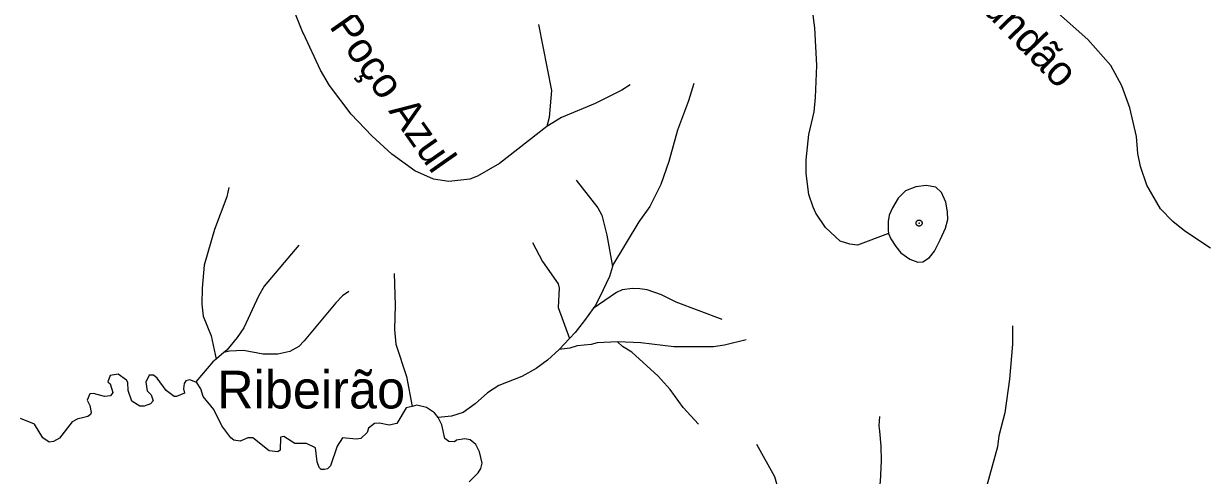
# Model space of a CAD drawing. Extents: x 393 to 446.6, y 8175.5 to 8231.
# Drawn here: x 405.92 to 412.17, y 8208.07 to 8210.46 of the extents above; entities that cross this region are included whole.
import ezdxf
from ezdxf.enums import TextEntityAlignment as Align

# ---------------------------------------------------------------- set-up
doc = ezdxf.new("R2010")
doc.units = 0
doc.header["$LTSCALE"] = 0.064
doc.header["$PDMODE"] = 32
doc.header["$PDSIZE"] = 0.032
doc.linetypes.add('LONG_DASHED', pattern=[7.5, 6, -1.5])
for name, color, linetype, lineweight in [('3', 7, 'LONG_DASHED', 25), ('7', 7, 'Continuous', 25), ('9', 7, 'LONG_DASHED', 25)]:
    doc.layers.add(name, color=color, linetype=linetype, lineweight=lineweight)
doc.layers.add('61', color=7, linetype='Continuous')

msp = doc.modelspace()

# ---------------------------------------------------------------- linework, layer by layer
at = {"layer": '3'}
msp.add_lwpolyline([(410.5024, 8209.3478), (410.514, 8209.3198), (410.5416, 8209.2799), (410.5672, 8209.2461), (410.6153, 8209.2124), (410.6582, 8209.196), (410.6848, 8209.198), (410.7186, 8209.2216), (410.7462, 8209.2543), (410.7759, 8209.3147), (410.8045, 8209.3771), (410.8168, 8209.4221), (410.8148, 8209.463), (410.8055, 8209.5142), (410.783, 8209.5653), (410.7534, 8209.594), (410.7012, 8209.6032), (410.647, 8209.596), (410.5928, 8209.5735), (410.5539, 8209.5356), (410.5232, 8209.4845), (410.5058, 8209.4446), (410.5007, 8209.4119), (410.5007, 8209.3668)], close=True, dxfattribs=at)
msp.add_point((410.664, 8209.4036), dxfattribs=at)
at = {"layer": '7'}
for p, q in [((408.8118, 8208.7912), (408.7567, 8208.734)), ((406.9814, 8208.7171), (406.9403, 8208.6832))]:
    msp.add_line(p, q, dxfattribs=at)
for points in [[(409.4706, 8210.1427), (409.443, 8210.0503), (409.3849, 8209.8952), (409.338, 8209.7289), (409.296, 8209.6078), (409.2379, 8209.4915), (409.1798, 8209.4108), (409.0408, 8209.1786), (409.0393, 8209.1736)], [(408.8478, 8209.6304), (408.9618, 8209.4851), (408.9828, 8209.4463), (409.0102, 8209.3397), (409.0393, 8209.1736)], [(407.0083, 8209.5914), (406.9966, 8209.5432), (406.932, 8209.3688), (406.8771, 8209.1799), (406.8658, 8209.0588), (406.8642, 8208.9748), (406.8722, 8208.9102), (406.9142, 8208.8069), (406.9403, 8208.6832)], [(408.6156, 8209.3002), (408.6695, 8209.1992), (408.7519, 8209.0814), (408.7583, 8209.0588), (408.7519, 8208.9554), (408.8114, 8208.7922), (408.8118, 8208.7912)], [(407.3787, 8209.2865), (407.1952, 8209.0685), (407.1645, 8209.0168), (407.087, 8208.8488), (407.0515, 8208.7972), (406.9965, 8208.7296), (406.9814, 8208.7171)], [(407.8828, 8209.1361), (407.888, 8208.9683), (407.8847, 8208.8392), (407.8928, 8208.7616), (407.9493, 8208.5905), (407.9787, 8208.4323)], [(409.0393, 8209.1736), (409.0234, 8209.1205), (408.9733, 8209.0122), (408.9488, 8208.9657), (408.9381, 8208.951)], [(409.6206, 8208.893), (409.3768, 8208.985), (409.2993, 8209.0232), (409.2234, 8209.0506), (409.1847, 8209.0555), (409.1459, 8209.0571), (409.091, 8209.049), (409.0619, 8209.0361), (408.9382, 8208.951), (408.9381, 8208.951)], [(407.6435, 8209.0412), (407.6097, 8209.018), (407.5747, 8208.9812), (407.4068, 8208.7794), (407.3777, 8208.7503), (407.3309, 8208.7229), (407.2663, 8208.7083), (407.1888, 8208.7099), (407.0854, 8208.7293), (407.0111, 8208.7245), (406.9814, 8208.7171)], [(408.9381, 8208.951), (408.8923, 8208.8876), (408.8423, 8208.823), (408.8118, 8208.7912)], [(409.0673, 8208.7738), (408.9586, 8208.7697), (408.9263, 8208.76), (408.852, 8208.7535), (408.8133, 8208.7406), (408.7567, 8208.734)], [(409.7485, 8208.7858), (409.6336, 8208.7568), (409.5754, 8208.7487), (409.3655, 8208.7487), (409.1895, 8208.7697), (409.0673, 8208.7738)], [(409.4964, 8208.3379), (409.4139, 8208.4258), (409.3461, 8208.5227), (409.2815, 8208.5921), (409.1427, 8208.7196), (409.0926, 8208.7503), (409.0673, 8208.7738)], [(406.9403, 8208.6832), (406.922, 8208.668), (406.8328, 8208.5617), (406.8324, 8208.5613)], [(408.7567, 8208.734), (408.6954, 8208.6776), (408.6356, 8208.6324), (408.5597, 8208.5904), (408.4386, 8208.5436), (408.3773, 8208.5048), (408.3127, 8208.4451), (408.2497, 8208.3999), (408.1867, 8208.3805), (408.1158, 8208.3731)], [(406.8324, 8208.5613), (406.8005, 8208.573), (406.7802, 8208.5679), (406.7705, 8208.5533), (406.7673, 8208.5259), (406.7721, 8208.5033), (406.7302, 8208.4855), (406.7173, 8208.4855), (406.6752, 8208.5162), (406.6284, 8208.5824), (406.609, 8208.5969), (406.5848, 8208.5985), (406.5671, 8208.5614), (406.5751, 8208.5146), (406.5961, 8208.4935), (406.6058, 8208.4613), (406.5929, 8208.4451), (406.559, 8208.4338), (406.5364, 8208.4338), (406.4944, 8208.4596), (406.4734, 8208.5162), (406.4718, 8208.5581), (406.4653, 8208.5711), (406.4217, 8208.6034), (406.3781, 8208.5953), (406.3668, 8208.563), (406.3781, 8208.5517), (406.3927, 8208.5065), (406.3814, 8208.4887), (406.3491, 8208.4839), (406.2909, 8208.5), (406.2715, 8208.4984), (406.257, 8208.4645), (406.2715, 8208.437), (406.278, 8208.3999), (406.2748, 8208.3886), (406.2602, 8208.3789), (406.2259, 8208.3706), (406.207, 8208.366), (406.1779, 8208.3499), (406.1101, 8208.2643), (406.0778, 8208.2465), (406.0552, 8208.2433), (406.0213, 8208.2659), (405.9777, 8208.3386), (405.9034, 8208.3676)], [(407.9787, 8208.4323), (407.9477, 8208.4241), (407.8977, 8208.3418), (407.8573, 8208.3321), (407.8056, 8208.3434), (407.7798, 8208.3418), (407.7477, 8208.3166), (407.7395, 8208.2933), (407.7071, 8208.2627), (407.6829, 8208.2594), (407.6102, 8208.2659), (407.5811, 8208.2223), (407.5456, 8208.1173), (407.5295, 8208.1012), (407.515, 8208.0979), (407.4972, 8208.0979), (407.4859, 8208.1093), (407.4746, 8208.1383), (407.4665, 8208.2126), (407.4181, 8208.2352), (407.3567, 8208.2352), (407.2986, 8208.2723), (407.2808, 8208.2691), (407.2792, 8208.2013), (407.2679, 8208.1916), (407.221, 8208.1964), (407.1339, 8208.2659), (407.108, 8208.2659), (407.0676, 8208.2481), (407.0337, 8208.253), (407.0176, 8208.2659), (406.9708, 8208.3289), (406.9272, 8208.4161), (406.8723, 8208.4839), (406.8593, 8208.5259), (406.8354, 8208.5602), (406.8324, 8208.5613)], [(408.1158, 8208.3731), (408.0962, 8208.3983), (408.0543, 8208.4258), (408.0026, 8208.4386), (407.9787, 8208.4323)], [(408.2803, 8208.0333), (408.3288, 8208.0802), (408.3417, 8208.1028), (408.3498, 8208.1319), (408.3353, 8208.1916), (408.3159, 8208.2303), (408.2868, 8208.2546), (408.2578, 8208.261), (408.2141, 8208.253), (408.2028, 8208.2449), (408.1722, 8208.2465), (408.1512, 8208.2626), (408.135, 8208.3353), (408.1158, 8208.3731)]]:
    msp.add_lwpolyline(points, dxfattribs=at)
at = {"layer": '9'}
for points in [[(408.6926, 8209.915), (408.4419, 8209.7192), (408.3256, 8209.6514), (408.2836, 8209.6368), (408.1738, 8209.6239), (408.0914, 8209.6369), (407.9929, 8209.6804), (407.8702, 8209.7692), (407.7652, 8209.8661), (407.6554, 8209.9808), (407.5408, 8210.1326), (407.4924, 8210.2133), (407.4032, 8210.4073), (407.4003, 8210.4136), (407.3324, 8210.5815), (407.2986, 8210.6429), (407.2864, 8210.6586)], [(410.5024, 8209.3478), (410.3378, 8209.2871), (410.2981, 8209.2918), (410.2467, 8209.3081), (410.1681, 8209.3801), (410.118, 8209.456), (410.1034, 8209.4883), (410.0809, 8209.5545), (410.0663, 8209.6659), (410.0663, 8209.7386), (410.0808, 8209.8726), (410.1083, 8209.9921), (410.1148, 8210.0696), (410.1221, 8210.2392), (410.1115, 8210.4378), (410.0857, 8210.6396)], [(413.2766, 8208.7701), (413.1523, 8208.7975), (412.8696, 8208.9085), (412.805, 8208.9457), (412.5999, 8209.0394), (412.2076, 8209.2703), (412.0719, 8209.3607), (412.0089, 8209.4124), (411.9427, 8209.4786), (411.87, 8209.6046), (411.8362, 8209.7031), (411.8232, 8209.7725), (411.8151, 8209.8629), (411.7812, 8210.0147), (411.7376, 8210.131), (411.6795, 8210.2392), (411.5584, 8210.3764), (411.2725, 8210.6299)], [(408.6485, 8210.4559), (408.7163, 8210.1052), (408.705, 8209.963), (408.6926, 8209.915)], [(409.1338, 8210.1366), (409.0894, 8210.1084), (408.9489, 8210.0373), (408.7696, 8209.9631), (408.6926, 8209.915)], [(411.1587, 8208.8589), (411.1595, 8208.7616), (411.1434, 8208.5759), (411.1192, 8208.3983), (411.0869, 8208.2772), (411.0804, 8208.2174), (411.0223, 8208.014), (410.9835, 8207.922), (410.9302, 8207.8428), (410.8608, 8207.7669), (410.8269, 8207.7395), (410.7381, 8207.691), (410.659, 8207.662), (410.5669, 8207.6377), (410.4393, 8207.6167)], [(410.4537, 8208.3794), (410.4506, 8208.3289), (410.4536, 8208.3009), (410.4619, 8208.2223), (410.4635, 8208.1448), (410.4571, 8208.0318), (410.4361, 8207.9171), (410.4361, 8207.7702), (410.4449, 8207.6915), (410.4393, 8207.6167)], [(409.8036, 8208.2328), (409.8984, 8208.0608), (409.9242, 8207.9672), (409.9436, 8207.7766), (409.9445, 8207.7727), (409.9597, 8207.7088), (409.9791, 8207.5505), (409.9575, 8207.3625)]]:
    msp.add_lwpolyline(points, dxfattribs=at)

# ---------------------------------------------------------------- texts
at = {"layer": '61'}
for s, rotation, p in [('Córrego do Fundão', 314.17, (410.7593, 8210.7737)), ('Córrego Poço Azul', 305.059, (407.5735, 8210.3919))]:
    msp.add_text(s, height=0.16, rotation=rotation, dxfattribs=at).set_placement(p, align=Align.CENTER)
msp.add_text('Ribeirão', height=0.2, dxfattribs=at).set_placement((407.4435, 8208.4214), align=Align.CENTER)

doc.saveas('drawing.dxf')
